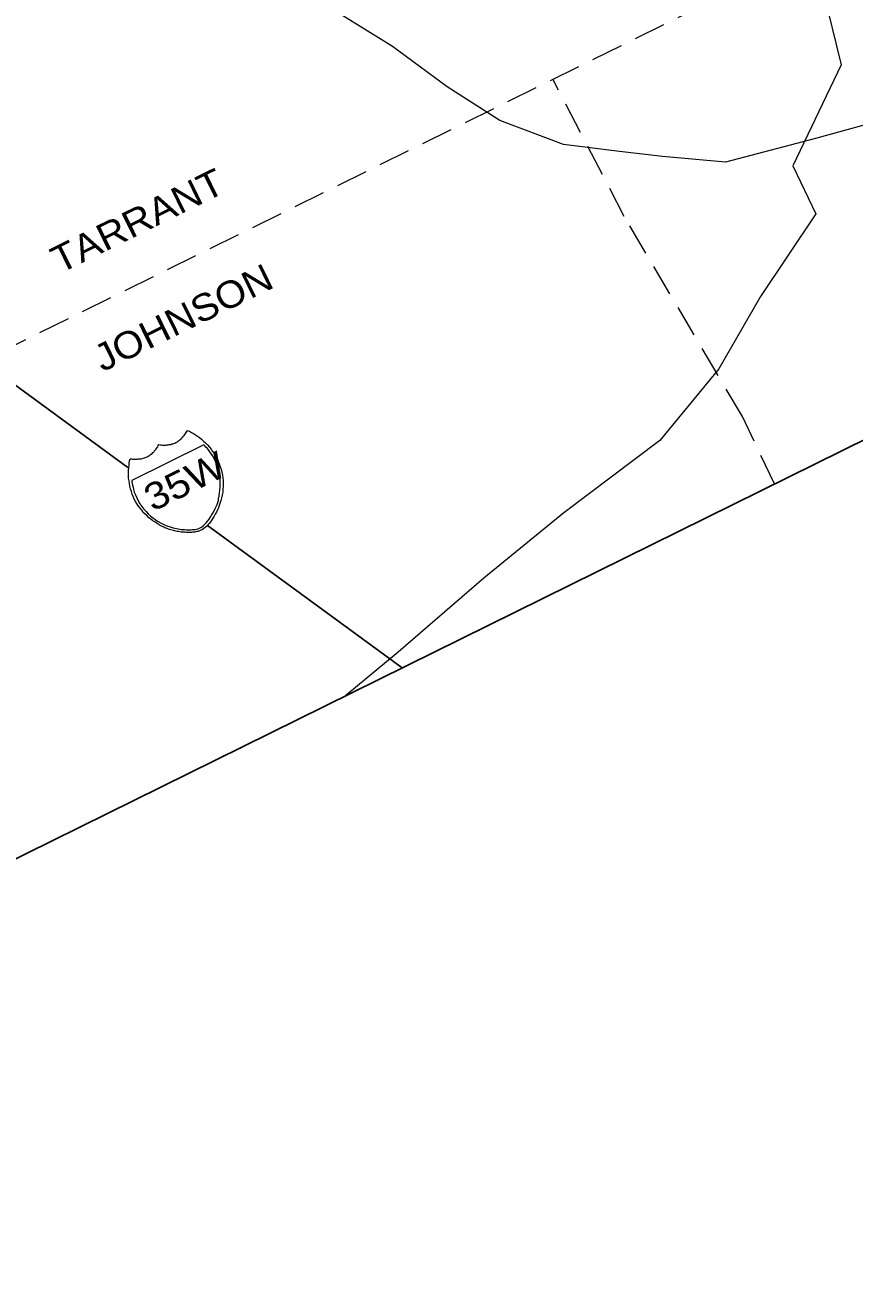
# Model space of a CAD drawing. Extents: x 2356606 to 2371222, y 6973096 to 6982644.
# Drawn here: x 2370979.1 to 2371136.4, y 6980110.7 to 6980347 of the extents above; entities that cross this region are included whole.
import ezdxf

# ---------------------------------------------------------------- set-up
doc = ezdxf.new("R2010")
doc.units = 0
doc.header["$LTSCALE"] = 2
doc.linetypes.add('MEDIUM_DASHED', pattern=[4.5, 3, -1.5])
doc.layers.add('62', color=7, linetype='Continuous', lineweight=13)
doc.layers.add('63', color=7, linetype='Continuous', lineweight=13)

msp = doc.modelspace()

# ---------------------------------------------------------------- linework, layer by layer
at = {"layer": '62', "linetype": 'MEDIUM_DASHED'}
msp.add_line((2370780.217, 6980189.078), (2371183.383, 6980388.055), dxfattribs=at)
at = {"layer": '62', "lineweight": 25}
msp.add_line((2371013.784, 6980252.029), (2371050.706, 6980225.061), dxfattribs=at)
for points in [[(2370613.001, 6980527.892), (2370818.917, 6980110.665), (2371222.081, 6980309.64), (2371016.165, 6980726.869)], [(2370885.051, 6980438.124), (2370907.53, 6980394.764), (2370932.824, 6980345.045), (2370969.992, 6980283.97), (2370998.654, 6980263.059)]]:
    msp.add_lwpolyline(points, dxfattribs=at)
at = {"layer": '62'}
for points in [[(2371129.79, 6980402.682), (2371128.751, 6980392.231), (2371127.643, 6980373.115), (2371130.492, 6980353.618), (2371134.01, 6980339.372), (2371124.844, 6980320.22), (2371129.173, 6980311.136), (2371118.688, 6980295.474), (2371110.787, 6980281.739), (2371099.577, 6980268.15), (2371081.351, 6980254.436), (2371066.173, 6980242.076), (2371049.917, 6980228.034), (2371040.012, 6980219.782)], [(2371147.148, 6980328.917), (2371138.571, 6980328.048), (2371129.118, 6980325.438), (2371112.027, 6980320.969), (2371100.06, 6980322.039), (2371091.911, 6980322.932), (2371081.3, 6980324.295), (2371069.258, 6980328.819), (2371059.239, 6980335.242), (2371048.852, 6980342.862), (2371035.27, 6980351.267), (2371024.817, 6980355.667), (2371015.947, 6980360.773), (2371005.588, 6980367.578), (2370999.855, 6980370.196), (2370987.882, 6980378.49)], [(2371005.418, 6980267.301), (2371005.622, 6980267.299), (2371005.843, 6980267.307), (2371006.013, 6980267.318), (2371006.234, 6980267.327), (2371006.436, 6980267.375), (2371006.627, 6980267.395), (2371006.808, 6980267.435), (2371006.999, 6980267.504), (2371007.18, 6980267.544), (2371007.383, 6980267.593), (2371007.545, 6980267.672), (2371007.728, 6980267.763), (2371007.888, 6980267.841), (2371008.047, 6980267.92), (2371008.229, 6980268.062), (2371008.352, 6980268.17), (2371008.503, 6980268.271), (2371008.665, 6980268.399), (2371008.817, 6980268.552), (2371008.959, 6980268.671), (2371009.1, 6980268.841), (2371009.232, 6980268.98), (2371009.354, 6980269.141), (2371009.475, 6980269.301), (2371009.597, 6980269.461), (2371009.728, 6980269.653), (2371009.849, 6980269.864), (2371009.953, 6980270.065), (2371010.332, 6980269.902), (2371010.706, 6980269.71), (2371011.086, 6980269.496), (2371011.485, 6980269.241), (2371011.859, 6980268.999), (2371012.249, 6980268.715), (2371012.632, 6980268.401), (2371013.022, 6980268.066), (2371013.402, 6980267.704), (2371013.763, 6980267.329), (2371014.111, 6980266.923), (2371014.431, 6980266.53), (2371014.741, 6980266.106), (2371015.051, 6980265.681), (2371015.302, 6980265.227), (2371015.573, 6980264.783), (2371015.78, 6980264.259), (2371016.008, 6980263.742), (2371016.178, 6980263.199), (2371016.344, 6980262.704), (2371016.505, 6980262.181), (2371016.582, 6980261.617), (2371016.67, 6980261.081), (2371016.727, 6980260.56), (2371016.744, 6980260.014), (2371016.742, 6980259.463), (2371016.7, 6980258.938), (2371016.665, 6980258.394), (2371016.563, 6980257.842), (2371016.446, 6980257.31), (2371016.315, 6980256.766), (2371016.13, 6980256.225), (2371016.007, 6980255.813), (2371015.855, 6980255.412), (2371015.66, 6980254.989), (2371015.476, 6980254.597), (2371015.243, 6980254.207), (2371015.009, 6980253.815), (2371014.786, 6980253.453), (2371014.564, 6980253.093), (2371014.33, 6980252.753), (2371014.078, 6980252.45), (2371013.825, 6980252.151), (2371013.564, 6980251.87), (2371013.318, 6980251.649), (2371013.066, 6980251.451), (2371012.803, 6980251.271), (2371012.571, 6980251.13)], [(2371012.571, 6980251.13), (2371012.399, 6980251.071), (2371012.259, 6980251.002), (2371012.089, 6980250.942), (2371011.928, 6980250.914), (2371011.745, 6980250.875), (2371011.564, 6980250.833), (2371011.331, 6980250.795), (2371011.119, 6980250.764), (2371010.92, 6980250.766), (2371010.708, 6980250.739), (2371010.454, 6980250.737), (2371010.233, 6980250.729), (2371009.992, 6980250.712), (2371009.783, 6980250.732), (2371009.518, 6980250.754), (2371009.267, 6980250.756), (2371009.027, 6980250.787), (2371008.764, 6980250.809), (2371008.516, 6980250.86), (2371008.273, 6980250.89), (2371008.03, 6980250.922), (2371007.771, 6980250.995), (2371007.528, 6980251.026), (2371007.297, 6980251.088), (2371007.036, 6980251.16), (2371006.805, 6980251.221), (2371006.575, 6980251.281), (2371006.353, 6980251.374), (2371006.092, 6980251.446), (2371005.881, 6980251.516), (2371005.679, 6980251.619), (2371005.459, 6980251.711), (2371005.058, 6980251.915), (2371004.604, 6980252.169), (2371004.205, 6980252.422), (2371003.805, 6980252.677), (2371003.394, 6980252.949), (2371003.003, 6980253.232), (2371002.633, 6980253.525), (2371002.291, 6980253.861), (2371001.93, 6980254.185), (2371001.58, 6980254.538), (2371001.279, 6980254.943), (2371000.97, 6980255.317), (2371000.649, 6980255.71), (2371000.4, 6980256.116), (2371000.121, 6980256.581), (2370999.869, 6980257.033), (2370999.682, 6980257.52), (2370999.493, 6980258.003), (2370999.325, 6980258.497), (2370999.174, 6980259), (2370999.058, 6980259.495), (2370998.951, 6980260.019), (2370998.872, 6980260.531), (2370998.794, 6980261.045), (2370998.787, 6980261.569), (2370998.768, 6980262.061), (2370998.782, 6980262.544), (2370998.813, 6980262.987), (2370998.876, 6980263.472), (2370998.9, 6980263.881), (2370998.993, 6980264.304), (2370999.095, 6980264.706), (2370999.316, 6980264.666), (2370999.557, 6980264.633), (2370999.79, 6980264.621), (2370999.992, 6980264.62), (2371000.213, 6980264.629), (2371000.413, 6980264.63), (2371000.625, 6980264.657), (2371000.827, 6980264.658), (2371001.006, 6980264.697), (2371001.198, 6980264.716), (2371001.399, 6980264.765), (2371001.571, 6980264.823), (2371001.794, 6980264.886), (2371001.955, 6980264.913), (2371002.116, 6980264.992), (2371002.317, 6980265.092), (2371002.478, 6980265.172), (2371002.64, 6980265.252), (2371002.801, 6980265.38), (2371002.943, 6980265.5), (2371003.094, 6980265.602), (2371003.235, 6980265.722), (2371003.408, 6980265.883), (2371003.552, 6980266.002), (2371003.673, 6980266.163), (2371003.804, 6980266.304), (2371003.946, 6980266.474), (2371004.087, 6980266.644), (2371004.209, 6980266.804), (2371004.321, 6980266.983), (2371004.424, 6980267.185), (2371004.544, 6980267.395), (2371004.764, 6980267.355), (2371004.986, 6980267.313), (2371005.218, 6980267.303), (2371005.418, 6980267.301)]]:
    msp.add_lwpolyline(points, dxfattribs=at)
at = {"layer": '62', "linetype": 'MEDIUM_DASHED'}
msp.add_lwpolyline([(2371121.353, 6980259.927), (2371115.241, 6980272.718), (2371092.843, 6980310.622), (2371079.281, 6980336.678)], dxfattribs=at)
at = {"layer": '62'}
msp.add_lwpolyline([(2371013.068, 6980267.313), (2370999.406, 6980260.569), (2370999.426, 6980260.329), (2370999.473, 6980260.027), (2370999.531, 6980259.705), (2370999.631, 6980259.299), (2370999.73, 6980258.846), (2370999.878, 6980258.344), (2371000.075, 6980257.839), (2371000.354, 6980257.271), (2371000.625, 6980256.729), (2371000.955, 6980256.161), (2371001.304, 6980255.658), (2371001.693, 6980255.172), (2371002.104, 6980254.696), (2371002.514, 6980254.272), (2371002.954, 6980253.837), (2371003.435, 6980253.472), (2371003.906, 6980253.128), (2371004.399, 6980252.794), (2371004.951, 6980252.488), (2371005.491, 6980252.204), (2371006.073, 6980251.991), (2371006.677, 6980251.784), (2371007.26, 6980251.62), (2371007.883, 6980251.478), (2371008.174, 6980251.394), (2371008.486, 6980251.372), (2371008.798, 6980251.3), (2371009.13, 6980251.288), (2371009.424, 6980251.257), (2371009.743, 6980251.216), (2371010.035, 6980251.235), (2371010.347, 6980251.213), (2371010.639, 6980251.23), (2371010.901, 6980251.261), (2371011.195, 6980251.279), (2371011.436, 6980251.297), (2371011.706, 6980251.355), (2371011.928, 6980251.416), (2371012.141, 6980251.496), (2371012.353, 6980251.576), (2371012.627, 6980251.736), (2371012.938, 6980251.963), (2371013.201, 6980252.244), (2371013.505, 6980252.546), (2371013.776, 6980252.854), (2371014.05, 6980253.217), (2371014.295, 6980253.588), (2371014.549, 6980253.987), (2371014.793, 6980254.411), (2371015.006, 6980254.841), (2371015.21, 6980255.242), (2371015.393, 6980255.634), (2371015.577, 6980256.025), (2371015.709, 6980256.417), (2371015.821, 6980256.801), (2371015.873, 6980257.102), (2371015.987, 6980257.685), (2371016.049, 6980258.218), (2371016.113, 6980258.749), (2371016.146, 6980259.292), (2371016.178, 6980259.787), (2371016.164, 6980260.282), (2371016.135, 6980260.742), (2371016.077, 6980261.216), (2371016.028, 6980261.669), (2371015.961, 6980262.111), (2371015.853, 6980262.537), (2371015.714, 6980262.968), (2371015.584, 6980263.382), (2371015.436, 6980263.785), (2371015.265, 6980264.181), (2371015.087, 6980264.542), (2371014.807, 6980265.11), (2371014.529, 6980265.573), (2371014.218, 6980265.999), (2371013.959, 6980266.371), (2371013.679, 6980266.685), (2371013.437, 6980266.918), (2371013.227, 6980267.14)], close=True, dxfattribs=at)
at = {"layer": '63', "linetype": 'MEDIUM_DASHED'}
msp.add_line((2370780.217, 6980189.078), (2371183.383, 6980388.055), dxfattribs=at)
at = {"layer": '63', "lineweight": 25}
msp.add_line((2371013.784, 6980252.029), (2371050.706, 6980225.061), dxfattribs=at)
for points in [[(2370613.001, 6980527.892), (2370818.917, 6980110.665), (2371222.081, 6980309.64), (2371016.165, 6980726.869)], [(2370885.051, 6980438.124), (2370907.53, 6980394.764), (2370932.824, 6980345.045), (2370969.992, 6980283.97), (2370998.654, 6980263.059)]]:
    msp.add_lwpolyline(points, dxfattribs=at)
at = {"layer": '63'}
for points in [[(2371129.79, 6980402.682), (2371128.751, 6980392.231), (2371127.643, 6980373.115), (2371130.492, 6980353.618), (2371134.01, 6980339.372), (2371124.844, 6980320.22), (2371129.173, 6980311.136), (2371118.688, 6980295.474), (2371110.787, 6980281.739), (2371099.577, 6980268.15), (2371081.351, 6980254.436), (2371066.173, 6980242.076), (2371049.917, 6980228.034), (2371040.012, 6980219.782)], [(2371147.148, 6980328.917), (2371138.571, 6980328.048), (2371129.118, 6980325.438), (2371112.027, 6980320.969), (2371100.06, 6980322.039), (2371091.911, 6980322.932), (2371081.3, 6980324.295), (2371069.258, 6980328.819), (2371059.239, 6980335.242), (2371048.852, 6980342.862), (2371035.27, 6980351.267), (2371024.817, 6980355.667), (2371015.947, 6980360.773), (2371005.588, 6980367.578), (2370999.855, 6980370.196), (2370987.882, 6980378.49)], [(2371005.418, 6980267.301), (2371005.622, 6980267.299), (2371005.843, 6980267.307), (2371006.013, 6980267.318), (2371006.234, 6980267.327), (2371006.436, 6980267.375), (2371006.627, 6980267.395), (2371006.808, 6980267.435), (2371006.999, 6980267.504), (2371007.18, 6980267.544), (2371007.383, 6980267.593), (2371007.545, 6980267.672), (2371007.728, 6980267.763), (2371007.888, 6980267.841), (2371008.047, 6980267.92), (2371008.229, 6980268.062), (2371008.352, 6980268.17), (2371008.503, 6980268.271), (2371008.665, 6980268.399), (2371008.817, 6980268.552), (2371008.959, 6980268.671), (2371009.1, 6980268.841), (2371009.232, 6980268.98), (2371009.354, 6980269.141), (2371009.475, 6980269.301), (2371009.597, 6980269.461), (2371009.728, 6980269.653), (2371009.849, 6980269.864), (2371009.953, 6980270.065), (2371010.332, 6980269.902), (2371010.706, 6980269.71), (2371011.086, 6980269.496), (2371011.485, 6980269.241), (2371011.859, 6980268.999), (2371012.249, 6980268.715), (2371012.632, 6980268.401), (2371013.022, 6980268.066), (2371013.402, 6980267.704), (2371013.763, 6980267.329), (2371014.111, 6980266.923), (2371014.431, 6980266.53), (2371014.741, 6980266.106), (2371015.051, 6980265.681), (2371015.302, 6980265.227), (2371015.573, 6980264.783), (2371015.78, 6980264.259), (2371016.008, 6980263.742), (2371016.178, 6980263.199), (2371016.344, 6980262.704), (2371016.505, 6980262.181), (2371016.582, 6980261.617), (2371016.67, 6980261.081), (2371016.727, 6980260.56), (2371016.744, 6980260.014), (2371016.742, 6980259.463), (2371016.7, 6980258.938), (2371016.665, 6980258.394), (2371016.563, 6980257.842), (2371016.446, 6980257.31), (2371016.315, 6980256.766), (2371016.13, 6980256.225), (2371016.007, 6980255.813), (2371015.855, 6980255.412), (2371015.66, 6980254.989), (2371015.476, 6980254.597), (2371015.243, 6980254.207), (2371015.009, 6980253.815), (2371014.786, 6980253.453), (2371014.564, 6980253.093), (2371014.33, 6980252.753), (2371014.078, 6980252.45), (2371013.825, 6980252.151), (2371013.564, 6980251.87), (2371013.318, 6980251.649), (2371013.066, 6980251.451), (2371012.803, 6980251.271), (2371012.571, 6980251.13)], [(2371012.571, 6980251.13), (2371012.399, 6980251.071), (2371012.259, 6980251.002), (2371012.089, 6980250.942), (2371011.928, 6980250.914), (2371011.745, 6980250.875), (2371011.564, 6980250.833), (2371011.331, 6980250.795), (2371011.119, 6980250.764), (2371010.92, 6980250.766), (2371010.708, 6980250.739), (2371010.454, 6980250.737), (2371010.233, 6980250.729), (2371009.992, 6980250.712), (2371009.783, 6980250.732), (2371009.518, 6980250.754), (2371009.267, 6980250.756), (2371009.027, 6980250.787), (2371008.764, 6980250.809), (2371008.516, 6980250.86), (2371008.273, 6980250.89), (2371008.03, 6980250.922), (2371007.771, 6980250.995), (2371007.528, 6980251.026), (2371007.297, 6980251.088), (2371007.036, 6980251.16), (2371006.805, 6980251.221), (2371006.575, 6980251.281), (2371006.353, 6980251.374), (2371006.092, 6980251.446), (2371005.881, 6980251.516), (2371005.679, 6980251.619), (2371005.459, 6980251.711), (2371005.058, 6980251.915), (2371004.604, 6980252.169), (2371004.205, 6980252.422), (2371003.805, 6980252.677), (2371003.394, 6980252.949), (2371003.003, 6980253.232), (2371002.633, 6980253.525), (2371002.291, 6980253.861), (2371001.93, 6980254.185), (2371001.58, 6980254.538), (2371001.279, 6980254.943), (2371000.97, 6980255.317), (2371000.649, 6980255.71), (2371000.4, 6980256.116), (2371000.121, 6980256.581), (2370999.869, 6980257.033), (2370999.682, 6980257.52), (2370999.493, 6980258.003), (2370999.325, 6980258.497), (2370999.174, 6980259), (2370999.058, 6980259.495), (2370998.951, 6980260.019), (2370998.872, 6980260.531), (2370998.794, 6980261.045), (2370998.787, 6980261.569), (2370998.768, 6980262.061), (2370998.782, 6980262.544), (2370998.813, 6980262.987), (2370998.876, 6980263.472), (2370998.9, 6980263.881), (2370998.993, 6980264.304), (2370999.095, 6980264.706), (2370999.316, 6980264.666), (2370999.557, 6980264.633), (2370999.79, 6980264.621), (2370999.992, 6980264.62), (2371000.213, 6980264.629), (2371000.413, 6980264.63), (2371000.625, 6980264.657), (2371000.827, 6980264.658), (2371001.006, 6980264.697), (2371001.198, 6980264.716), (2371001.399, 6980264.765), (2371001.571, 6980264.823), (2371001.794, 6980264.886), (2371001.955, 6980264.913), (2371002.116, 6980264.992), (2371002.317, 6980265.092), (2371002.478, 6980265.172), (2371002.64, 6980265.252), (2371002.801, 6980265.38), (2371002.943, 6980265.5), (2371003.094, 6980265.602), (2371003.235, 6980265.722), (2371003.408, 6980265.883), (2371003.552, 6980266.002), (2371003.673, 6980266.163), (2371003.804, 6980266.304), (2371003.946, 6980266.474), (2371004.087, 6980266.644), (2371004.209, 6980266.804), (2371004.321, 6980266.983), (2371004.424, 6980267.185), (2371004.544, 6980267.395), (2371004.764, 6980267.355), (2371004.986, 6980267.313), (2371005.218, 6980267.303), (2371005.418, 6980267.301)]]:
    msp.add_lwpolyline(points, dxfattribs=at)
at = {"layer": '63', "linetype": 'MEDIUM_DASHED'}
msp.add_lwpolyline([(2371121.353, 6980259.927), (2371115.241, 6980272.718), (2371092.843, 6980310.622), (2371079.281, 6980336.678)], dxfattribs=at)
at = {"layer": '63'}
msp.add_lwpolyline([(2371013.068, 6980267.313), (2370999.406, 6980260.569), (2370999.426, 6980260.329), (2370999.473, 6980260.027), (2370999.531, 6980259.705), (2370999.631, 6980259.299), (2370999.73, 6980258.846), (2370999.878, 6980258.344), (2371000.075, 6980257.839), (2371000.354, 6980257.271), (2371000.625, 6980256.729), (2371000.955, 6980256.161), (2371001.304, 6980255.658), (2371001.693, 6980255.172), (2371002.104, 6980254.696), (2371002.514, 6980254.272), (2371002.954, 6980253.837), (2371003.435, 6980253.472), (2371003.906, 6980253.128), (2371004.399, 6980252.794), (2371004.951, 6980252.488), (2371005.491, 6980252.204), (2371006.073, 6980251.991), (2371006.677, 6980251.784), (2371007.26, 6980251.62), (2371007.883, 6980251.478), (2371008.174, 6980251.394), (2371008.486, 6980251.372), (2371008.798, 6980251.3), (2371009.13, 6980251.288), (2371009.424, 6980251.257), (2371009.743, 6980251.216), (2371010.035, 6980251.235), (2371010.347, 6980251.213), (2371010.639, 6980251.23), (2371010.901, 6980251.261), (2371011.195, 6980251.279), (2371011.436, 6980251.297), (2371011.706, 6980251.355), (2371011.928, 6980251.416), (2371012.141, 6980251.496), (2371012.353, 6980251.576), (2371012.627, 6980251.736), (2371012.938, 6980251.963), (2371013.201, 6980252.244), (2371013.505, 6980252.546), (2371013.776, 6980252.854), (2371014.05, 6980253.217), (2371014.295, 6980253.588), (2371014.549, 6980253.987), (2371014.793, 6980254.411), (2371015.006, 6980254.841), (2371015.21, 6980255.242), (2371015.393, 6980255.634), (2371015.577, 6980256.025), (2371015.709, 6980256.417), (2371015.821, 6980256.801), (2371015.873, 6980257.102), (2371015.987, 6980257.685), (2371016.049, 6980258.218), (2371016.113, 6980258.749), (2371016.146, 6980259.292), (2371016.178, 6980259.787), (2371016.164, 6980260.282), (2371016.135, 6980260.742), (2371016.077, 6980261.216), (2371016.028, 6980261.669), (2371015.961, 6980262.111), (2371015.853, 6980262.537), (2371015.714, 6980262.968), (2371015.584, 6980263.382), (2371015.436, 6980263.785), (2371015.265, 6980264.181), (2371015.087, 6980264.542), (2371014.807, 6980265.11), (2371014.529, 6980265.573), (2371014.218, 6980265.999), (2371013.959, 6980266.371), (2371013.679, 6980266.685), (2371013.437, 6980266.918), (2371013.227, 6980267.14)], close=True, dxfattribs=at)

# ---------------------------------------------------------------- texts
at = {"layer": '62'}
for s, width, p in [('TARRANT', 1.1, (2370985.71, 6980299.706)), ('JOHNSON', 1.1, (2370993.846, 6980281.086)), ('35W', 1.15, (2371003.362, 6980254.589))]:
    msp.add_text(s, height=5.099, rotation=26.268, dxfattribs=dict(at, width=width)).set_placement(p)
at = {"layer": '63'}
for s, width, p in [('TARRANT', 1.1, (2370985.71, 6980299.706)), ('JOHNSON', 1.1, (2370993.846, 6980281.086)), ('35W', 1.15, (2371003.362, 6980254.589))]:
    msp.add_text(s, height=5.099, rotation=26.268, dxfattribs=dict(at, width=width)).set_placement(p)

doc.saveas('drawing.dxf')
